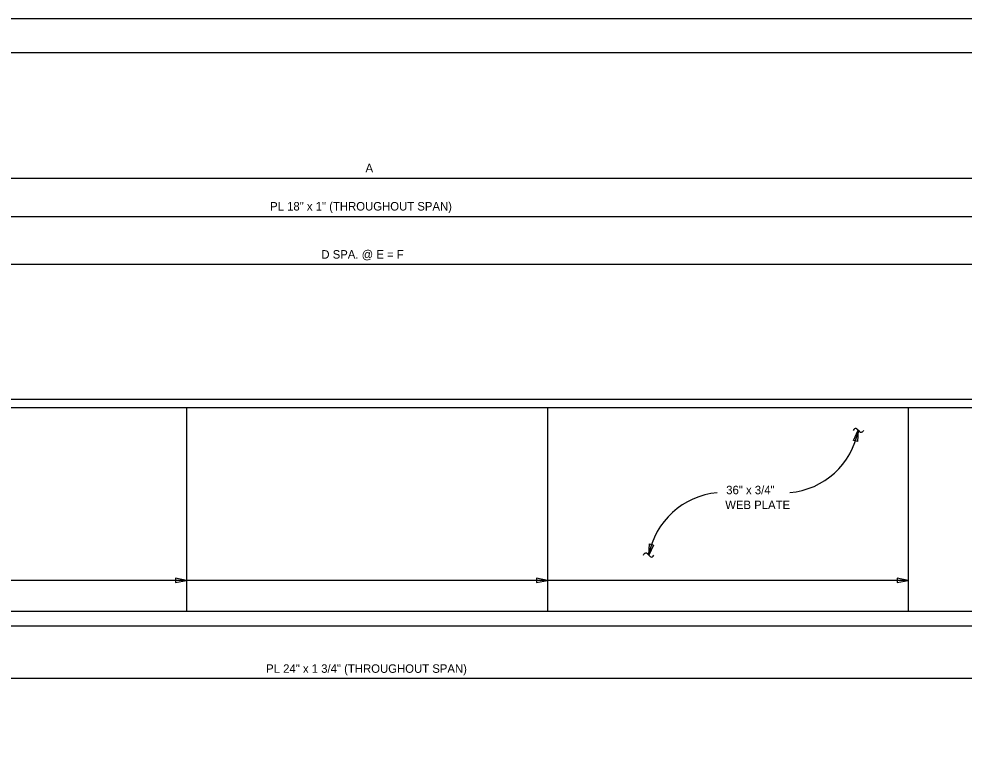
# Model space of a CAD drawing. Extents: x -305 to -161, y -187 to -99.
# Drawn here: x -251.4 to -195.6, y -143.5 to -99.5 of the extents above; entities that cross this region are included whole.
import ezdxf

# ---------------------------------------------------------------- set-up
doc = ezdxf.new("R2010")
doc.units = 0
for name, color, linetype in [('BR_AUTO DIMENSION', 7, 'Continuous'), ('BR_BORDER LINES', 7, 'Continuous'), ('BR_STRUCTURAL STEEL', 7, 'Continuous'), ('BR_TEXT', 7, 'Continuous'), ('Level 31', 7, 'Continuous')]:
    doc.layers.add(name, color=color, linetype=linetype)

msp = doc.modelspace()

# ---------------------------------------------------------------- linework, layer by layer
at = {"layer": 'BR_AUTO DIMENSION'}
for p, q in [((-284.888, -108.876), (-176.804, -108.876)), ((-284.888, -111.134), (-176.804, -111.134)), ((-178.304, -113.971), (-283.388, -113.971)), ((-198.921, -132.601), (-288.61, -132.601)), ((-284.888, -138.367), (-176.804, -138.367))]:
    msp.add_line(p, q, dxfattribs=at)
for points in [[(-202.158, -124.344), (-201.876, -123.746), (-201.916, -124.406)], [(-213.945, -130.513), (-214.227, -131.111), (-214.187, -130.451)], [(-242.138, -132.726), (-241.488, -132.601), (-242.138, -132.476)], [(-220.854, -132.726), (-220.204, -132.601), (-220.854, -132.476)], [(-199.571, -132.726), (-198.921, -132.601), (-199.571, -132.476)]]:
    msp.add_lwpolyline(points, close=True, dxfattribs=at)
for centre, start, end in [((-206.3, -122.942), 274.9624, 349.7037), ((-209.803, -131.915), 94.9624, 169.7037)]:
    msp.add_arc(centre, 4.497, start, end, dxfattribs=at)
at = {"layer": 'BR_BORDER LINES'}
msp.add_line((-163.178, -101.489), (-297.843, -101.489), dxfattribs=at)
at = {"layer": 'BR_STRUCTURAL STEEL'}
for p, q in [((-284.888, -121.912), (-176.804, -121.912)), ((-284.888, -122.412), (-176.804, -122.412)), ((-241.488, -122.412), (-241.488, -134.412)), ((-220.204, -122.412), (-220.204, -134.412)), ((-198.921, -122.412), (-198.921, -134.412)), ((-284.888, -134.412), (-176.804, -134.412)), ((-284.888, -135.287), (-176.804, -135.287))]:
    msp.add_line(p, q, dxfattribs=at)
at = {"layer": 'BR_TEXT'}
for p, q in [((-202.136, -123.693), (-202.178, -123.754)), ((-201.794, -123.82), (-201.957, -123.671)), ((-201.561, -123.754), (-201.591, -123.8)), ((-214.542, -131.103), (-214.512, -131.057)), ((-214.309, -131.037), (-214.146, -131.186)), ((-213.967, -131.164), (-213.925, -131.103))]:
    msp.add_line(p, q, dxfattribs=at)
for centre, radius, start, end in [((-202.038, -123.746), 0.111, 43.4519, 151.7375), ((-201.701, -123.739), 0.125, 221.007, 330.8059), ((-214.402, -131.118), 0.125, 41.007, 150.8059), ((-214.065, -131.111), 0.111, 223.4519, 331.7375)]:
    msp.add_arc(centre, radius, start, end, dxfattribs=at)
at = {"layer": 'Level 31'}
msp.add_lwpolyline([(-305.176, -187.489), (-161.176, -187.489), (-161.176, -99.489), (-305.176, -99.489)], close=True, dxfattribs=at)

# ---------------------------------------------------------------- texts
at = {"layer": 'BR_AUTO DIMENSION'}
for s, p in [('A', (-230.936, -108.53)), ('PL 18" x 1" (THROUGHOUT SPAN)', (-236.567, -110.788)), ('D SPA. @ E = F', (-233.542, -113.625)), ('36" x 3/4" ', (-209.661, -127.518)), ('WEB PLATE', (-209.72, -128.393)), ('PL 24" x 1 3/4" (THROUGHOUT SPAN)', (-236.8, -138.048))]:
    msp.add_text(s, height=0.5, rotation=360, dxfattribs=at).set_placement(p)

doc.saveas('drawing.dxf')
